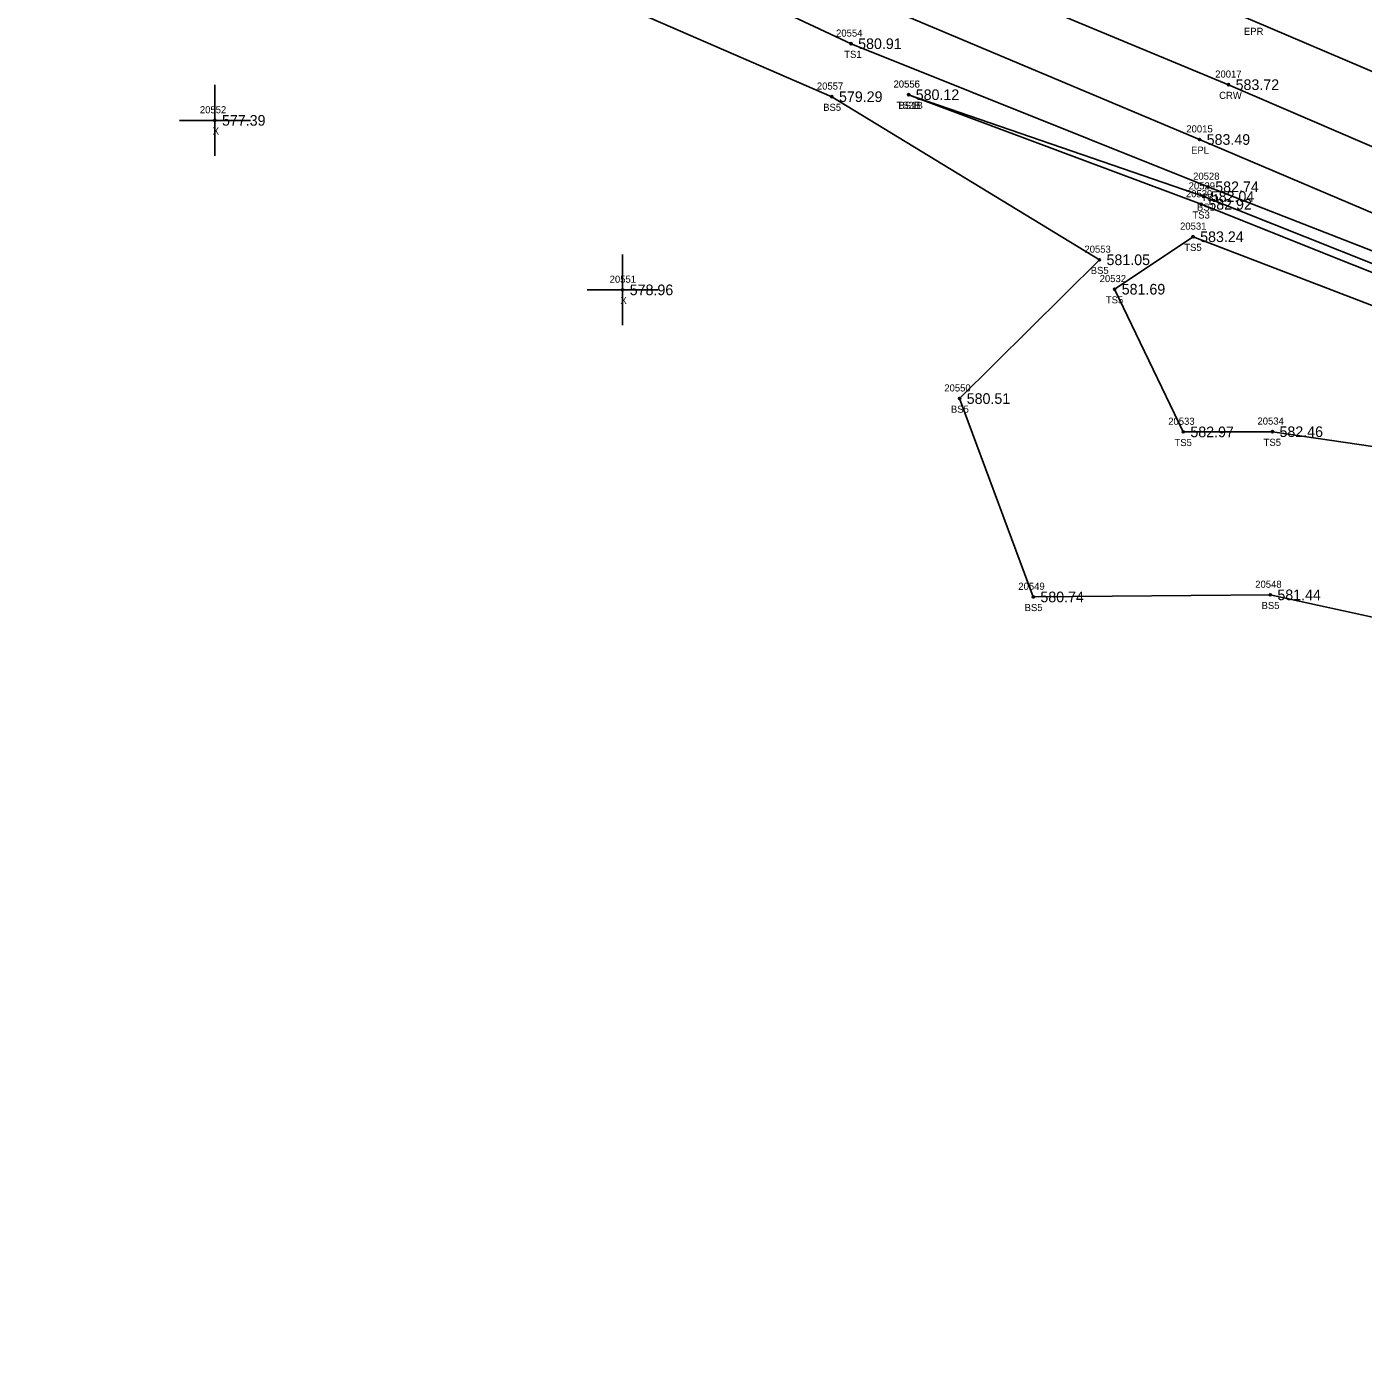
# Model space of a CAD drawing. Extents: x 1664837 to 1666270, y 987403 to 988245.
# Drawn here: x 1665759.5 to 1665947.9, y 987404.8 to 987594.7 of the extents above; entities that cross this region are included whole.
import ezdxf

# ---------------------------------------------------------------- set-up
doc = ezdxf.new("R2010")
doc.units = 0
for name, color, linetype in [('RD_DTM_BkLn1', 7, 'Continuous'), ('RD_DTM_BkLn2', 7, 'Continuous'), ('RD_DTM_BkLn_txCode', 7, 'Continuous'), ('RD_EX_Misc', 7, 'Continuous'), ('RD_EX_Misc_txCode', 7, 'Continuous'), ('RD_EX_Road', 7, 'Continuous'), ('RD_EX_Road_txCode', 7, 'Continuous'), ('RD_EX_TX_Misc_ELEV', 7, 'Continuous'), ('RD_EX_TX_Road_ELEV', 7, 'Continuous'), ('RD_HC_Survey_ELEV', 7, 'Continuous'), ('RD_HC_Survey_txCode', 7, 'Continuous'), ('RD_SMD_Locator', 7, 'Continuous')]:
    doc.layers.add(name, color=color, linetype=linetype)

msp = doc.modelspace()

# ---------------------------------------------------------------- linework, layer by layer
at = {"layer": 'RD_DTM_BkLn1'}
msp.add_lwpolyline([(1666158.65, 987488.74), (1666112.69, 987508.17), (1666066.71, 987527.94), (1666020.54, 987547.08), (1665974.85, 987566.77), (1665928.96, 987586.52), (1665882.66, 987605.79), (1665836.76, 987625.38), (1665790.86, 987644.81), (1665744.75, 987663.93), (1665698.8, 987683.39), (1665652.93, 987702.82), (1665606.7, 987721.88), (1665561.04, 987742.04), (1665527.67, 987755.89)], dxfattribs=at)
at = {"layer": 'RD_DTM_BkLn2'}
for points in [[(1666152.82, 987476.83), (1666108.53, 987496.54), (1666062.68, 987516.61), (1666015.91, 987535.8), (1665969.55, 987555.16), (1665926.09, 987572.12), (1665875.73, 987592.3), (1665829.7, 987613.88), (1665783.86, 987631.56), (1665738.66, 987650.04), (1665693.22, 987670.26), (1665645.99, 987690.14), (1665601.24, 987708.82), (1665555.03, 987727.9), (1665522.94, 987740.22)], [(1666117.29, 987404.85), (1666064.63, 987440.28), (1666022.87, 987464.18), (1665976.62, 987505.49), (1665934.85, 987514.58), (1665901.43, 987514.29), (1665891.04, 987542.26), (1665910.76, 987561.83), (1665873.03, 987584.83), (1665826.13, 987605.22), (1665781.49, 987626.06), (1665735.29, 987642.75), (1665690.09, 987662.74), (1665646.61, 987681.64)], [(1666152.2, 987475.35), (1666107.72, 987494.78), (1666061.84, 987514.6), (1666015.3, 987534.28), (1665968.59, 987553.61), (1665925.46, 987570.75), (1665883.85, 987585.11)], [(1666152.71, 987474.36), (1666107.47, 987494.11), (1666061.41, 987513.49), (1666014.8, 987533.07), (1665968.17, 987552.49), (1665925.11, 987569.65), (1665883.85, 987585.11)], [(1666150.69, 987471.63), (1666103.73, 987485.25), (1666058.87, 987509.16), (1666012.36, 987528.21), (1665967.23, 987548.46), (1665923.96, 987565.08), (1665912.9, 987557.68), (1665922.58, 987537.56), (1665935.15, 987537.59), (1665963.45, 987533.43), (1666001.19, 987518.01), (1666046.03, 987494.86), (1666073.68, 987482.38), (1666094.38, 987450.1), (1666143.23, 987423.22)]]:
    msp.add_lwpolyline(points, dxfattribs=at)
at = {"layer": 'RD_EX_Misc'}
for p, q in [((1665786.02, 987576.49), (1665786.02, 987586.49)), ((1665781.02, 987581.49), (1665791.02, 987581.49)), ((1665843.52, 987552.59), (1665843.52, 987562.59)), ((1665838.52, 987557.59), (1665848.52, 987557.59))]:
    msp.add_line(p, q, dxfattribs=at)
at = {"layer": 'RD_EX_Road'}
for points in [[(1666163.18, 987497.62), (1666116.6, 987517.39), (1666070.7, 987536.94), (1666024.42, 987556.43), (1665979.02, 987575.67), (1665932.35, 987595.55), (1665886.93, 987614.54), (1665839.87, 987634.25), (1665794.5, 987653.27), (1665748.81, 987672.51), (1665702.36, 987691.87), (1665656.42, 987711.45), (1665610.33, 987731.03), (1665564.85, 987750.93), (1665531.47, 987764.82)], [(1666156.67, 987480.61), (1666109.28, 987500.74), (1666063.55, 987520.04), (1666017.04, 987539.82), (1665971.11, 987559.14), (1665924.88, 987578.79), (1665879.5, 987597.89), (1665833.22, 987617.38), (1665786.91, 987636.81), (1665741.44, 987656.13), (1665695.81, 987675.2), (1665649.26, 987694.85), (1665603.56, 987714.71), (1665558.4, 987733.87), (1665524.71, 987748.93)]]:
    msp.add_lwpolyline(points, dxfattribs=at)
at = {"layer": 'RD_SMD_Locator'}
for centre in [(1665875.73, 987592.3), (1665928.96, 987586.52), (1665873.03, 987584.83), (1665883.85, 987585.11), (1665883.85, 987585.11), (1665786.02, 987581.49), (1665924.88, 987578.79), (1665926.09, 987572.12), (1665925.11, 987569.65), (1665925.46, 987570.75), (1665923.96, 987565.08), (1665910.76, 987561.83), (1665843.52, 987557.59), (1665912.9, 987557.68), (1665891.04, 987542.26), (1665922.58, 987537.56), (1665935.15, 987537.59), (1665901.43, 987514.29), (1665934.85, 987514.58)]:
    msp.add_circle(centre, 0.15, dxfattribs=at)

# ---------------------------------------------------------------- texts
at = {"layer": 'RD_DTM_BkLn_txCode'}
for s, p in [('20554', (1665873.62, 987593.3)), ('TS1', (1665874.77, 987590.3)), ('20557', (1665870.91, 987585.83)), ('20556', (1665881.71, 987586.11)), ('20555', (1665881.73, 987586.11)), ('BS5', (1665871.8, 987582.83)), ('TS3B', (1665882.14, 987583.11)), ('BS1B', (1665882.43, 987583.11)), ('20528', (1665923.97, 987573.12)), ('20530', (1665922.95, 987570.65)), ('20529', (1665923.34, 987571.75)), ('TS1', (1665925.12, 987570.12)), ('BS1', (1665924.51, 987568.75)), ('TS3', (1665923.87, 987567.65)), ('20531', (1665922.13, 987566.08)), ('20553', (1665908.64, 987562.83)), ('TS5', (1665922.72, 987563.08)), ('BS5', (1665909.53, 987559.83)), ('20532', (1665910.79, 987558.68)), ('TS5', (1665911.66, 987555.68)), ('20550', (1665888.88, 987543.26)), ('BS5', (1665889.81, 987540.26)), ('20533', (1665920.46, 987538.56)), ('20534', (1665933.04, 987538.59)), ('TS5', (1665921.34, 987535.56)), ('TS5', (1665933.91, 987535.59)), ('20549', (1665899.32, 987515.29)), ('20548', (1665932.73, 987515.58)), ('BS5', (1665900.21, 987512.29)), ('BS5', (1665933.62, 987512.58))]:
    msp.add_text(s, height=1, dxfattribs=at).set_placement(p)
at = {"layer": 'RD_EX_Misc_txCode'}
for s, p in [('20552', (1665783.9, 987582.49)), ('X', (1665785.71, 987579.49)), ('20551', (1665841.69, 987558.59)), ('X', (1665843.21, 987555.59))]:
    msp.add_text(s, height=1, dxfattribs=at).set_placement(p)
at = {"layer": 'RD_EX_Road_txCode'}
for s, p in [('EPR', (1665931.13, 987593.55)), ('20015', (1665923.01, 987579.79)), ('EPL', (1665923.68, 987576.79))]:
    msp.add_text(s, height=1, dxfattribs=at).set_placement(p)
at = {"layer": 'RD_EX_TX_Misc_ELEV'}
for s, p in [('580.91', (1665876.73, 987591.55)), ('579.29', (1665874.03, 987584.08)), ('580.12', (1665884.85, 987584.36)), ('580.12', (1665884.85, 987584.36)), ('577.39', (1665787.02, 987580.74)), ('582.74', (1665927.09, 987571.37)), ('582.04', (1665926.46, 987570)), ('582.92', (1665926.11, 987568.9)), ('583.24', (1665924.96, 987564.33)), ('581.05', (1665911.76, 987561.08)), ('578.96', (1665844.52, 987556.84)), ('581.69', (1665913.9, 987556.93)), ('580.51', (1665892.04, 987541.51)), ('582.97', (1665923.58, 987536.81)), ('582.46', (1665936.15, 987536.84)), ('580.74', (1665902.43, 987513.54)), ('581.44', (1665935.85, 987513.83))]:
    msp.add_text(s, height=1.5, dxfattribs=at).set_placement(p)
at = {"layer": 'RD_EX_TX_Road_ELEV'}
msp.add_text('583.49', height=1.5, dxfattribs=at).set_placement((1665925.88, 987578.04))
at = {"layer": 'RD_HC_Survey_ELEV'}
msp.add_text('583.72', height=1.5, dxfattribs=at).set_placement((1665929.96, 987585.77))
at = {"layer": 'RD_HC_Survey_txCode'}
for s, p in [('20017', (1665927.08, 987587.52)), ('CRW', (1665927.64, 987584.52))]:
    msp.add_text(s, height=1, dxfattribs=at).set_placement(p)

doc.saveas('drawing.dxf')
